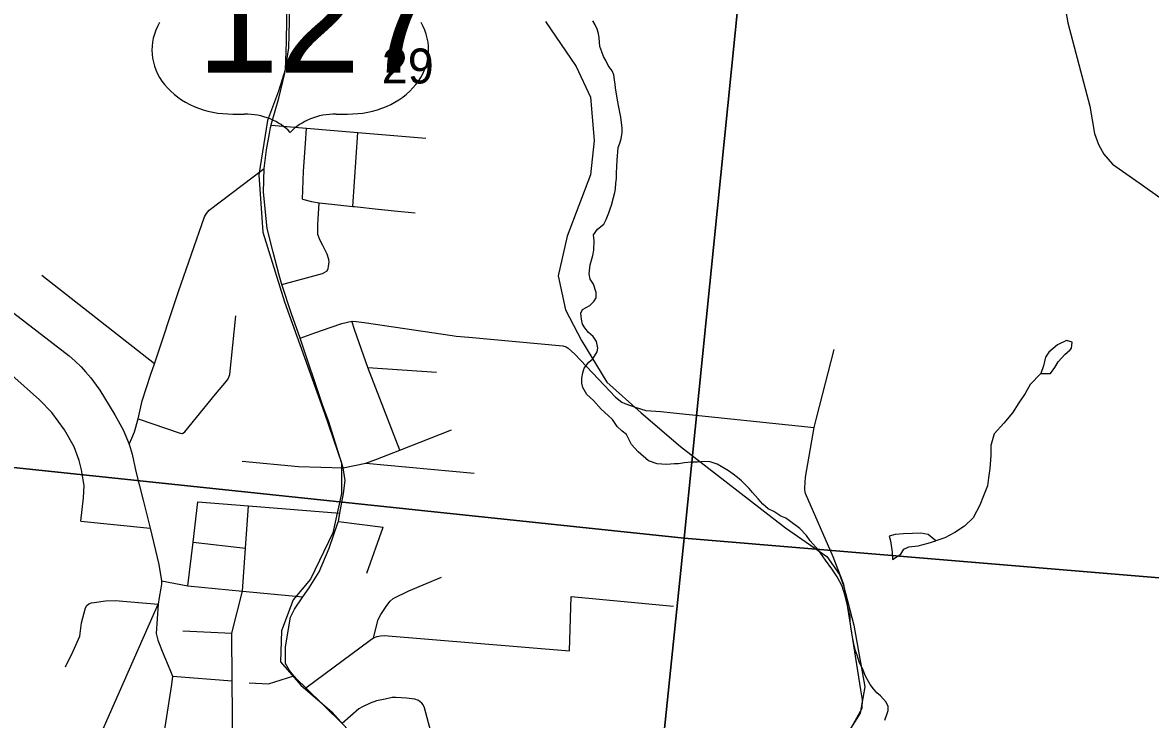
# Model space of a CAD drawing. Extents: x -8.2 to 38.5, y -0.1 to 21.9.
# Drawn here: x 5.146 to 6.498, y 18.858 to 19.692 of the extents above; entities that cross this region are included whole.
import ezdxf

# ---------------------------------------------------------------- set-up
doc = ezdxf.new("R2010")
doc.units = 0
for name, color, linetype in [('GM_X_Adjacent_County_Text', 7, 'Continuous'), ('GM_X_Airport_Location_Class_3', 7, 'Continuous'), ('GM_X_County_Road_Text', 7, 'Continuous'), ('GM_X_Minor_Lake_Text', 7, 'Continuous'), ('GM_X_Minor_River', 7, 'Continuous'), ('GM_X_Township_Road_Text', 7, 'Continuous'), ('GM_X_Township_Subdivision', 7, 'Continuous'), ('GM_X_Township_Subdivision_Text', 7, 'Continuous'), ('GM_X_Township_Text', 7, 'Continuous'), ('GM_X_US_Location', 7, 'Continuous')]:
    doc.layers.add(name, color=color, linetype=linetype)

msp = doc.modelspace()

# ---------------------------------------------------------------- linework, layer by layer
at = {"layer": 'GM_X_Adjacent_County_Text'}
for points in [[(5.0467, 20.1811), (6.0401, 20.072), (5.9396, 19.0747), (4.9457, 19.1792)], [(7.0485, 19.9899), (6.9585, 18.9896), (5.9396, 19.0747), (6.0401, 20.072)], [(5.9396, 19.0747), (5.838, 18.0925), (4.8395, 18.1926), (4.9457, 19.1792)], [(5.9396, 19.0747), (6.9585, 18.9896), (6.8589, 17.9964), (5.838, 18.0925)]]:
    msp.add_lwpolyline(points, close=True, dxfattribs=at)
at = {"layer": 'GM_X_Airport_Location_Class_3'}
for points in [[(5.466, 19.6771), (5.4665, 19.6943), (5.4664, 19.7372), (5.4662, 19.7608), (5.4686, 19.7892), (5.4775, 19.8481), (5.4791, 19.878), (5.4789, 19.9088), (5.4743, 19.9356), (5.47, 19.9472)], [(5.4425, 19.5595), (5.4438, 19.5666), (5.4444, 19.5694), (5.4448, 19.5715), (5.4535, 19.6017), (5.4608, 19.6318), (5.4655, 19.662), (5.466, 19.6771)], [(5.4469, 19.4173), (5.4398, 19.4458), (5.4351, 19.4893), (5.4361, 19.5177), (5.4388, 19.54), (5.4425, 19.5595)], [(5.4572, 19.3784), (5.4539, 19.3898), (5.4469, 19.4173)], [(5.4791, 19.3143), (5.4689, 19.3435), (5.4572, 19.3784)], [(5.5297, 18.8527), (5.4861, 18.8952), (5.4756, 18.9054), (5.4717, 18.9099), (5.4665, 18.9161), (5.4616, 18.9246), (5.4616, 18.9444), (5.4677, 18.9799), (5.4723, 18.9896), (5.4826, 19.0044), (5.49, 19.015), (5.5022, 19.0343), (5.514, 19.0627), (5.5248, 19.0941), (5.525, 19.0948), (5.5268, 19.1045), (5.5312, 19.1281), (5.533, 19.1436), (5.5308, 19.1589), (5.5135, 19.2139), (5.5062, 19.2344), (5.4791, 19.3143)]]:
    msp.add_lwpolyline(points, dxfattribs=at)
at = {"layer": 'GM_X_Minor_Lake_Text'}
for points in [[(6.3671, 19.272), (6.3785, 19.2719), (6.3839, 19.279), (6.3879, 19.2858), (6.3957, 19.2947), (6.4022, 19.3002), (6.4038, 19.3021), (6.4047, 19.3093), (6.3979, 19.3114), (6.3872, 19.3063), (6.3767, 19.2974), (6.3728, 19.2914), (6.3703, 19.2812)], [(6.3703, 19.2812), (6.3671, 19.272)], [(6.2414, 19.0716), (6.2321, 19.0792), (6.2234, 19.0805), (6.2132, 19.0804), (6.2025, 19.0799), (6.1926, 19.0789), (6.1854, 19.0772), (6.1868, 19.0715), (6.1888, 19.0578), (6.1893, 19.049), (6.1993, 19.0556), (6.2029, 19.0616), (6.209, 19.0641), (6.2201, 19.0654), (6.2319, 19.0686)], [(6.2319, 19.0686), (6.2414, 19.0716)]]:
    msp.add_lwpolyline(points, dxfattribs=at)
at = {"layer": 'GM_X_Minor_River'}
for points in [[(5.831, 19.4381), (5.8357, 19.4448), (5.8431, 19.4507), (5.8459, 19.4563), (5.8492, 19.4642), (5.8508, 19.4691), (5.8525, 19.4737), (5.855, 19.4827), (5.8563, 19.4888), (5.8572, 19.4933), (5.8577, 19.4998), (5.8583, 19.5055), (5.8584, 19.512), (5.859, 19.5199), (5.8592, 19.5275), (5.8604, 19.5427), (5.8624, 19.548), (5.8641, 19.5529), (5.8651, 19.5605), (5.8652, 19.5658), (5.8637, 19.5792), (5.861, 19.593), (5.8593, 19.6018), (5.8574, 19.614), (5.8567, 19.6186), (5.8561, 19.6239), (5.8551, 19.6297), (5.8534, 19.6347), (5.8486, 19.6409), (5.8457, 19.6467), (5.8428, 19.6517), (5.8407, 19.6571), (5.8386, 19.6636), (5.8379, 19.669), (5.8377, 19.6739), (5.8367, 19.6793), (5.8353, 19.6843), (5.8328, 19.6897), (5.8302, 19.6943)], [(6.18, 18.8565), (6.1824, 18.8633), (6.1841, 18.8682), (6.1842, 18.8728), (6.1817, 18.8782), (6.175, 18.8856), (6.1706, 18.8895), (6.1665, 18.8942), (6.1625, 18.8992), (6.1567, 18.9093), (6.1531, 18.9185), (6.1499, 18.9255), (6.1471, 18.9343), (6.1449, 18.9397), (6.1429, 18.9482), (6.1412, 18.9562), (6.1399, 18.9658), (6.1387, 18.9745), (6.1385, 18.981), (6.1354, 18.9941), (6.1327, 19.0056), (6.1288, 19.0171), (6.123, 19.0283), (6.1164, 19.038), (6.1091, 19.0481), (6.1007, 19.0601), (6.0907, 19.0715), (6.0863, 19.078), (6.0782, 19.0863), (6.0659, 19.0954), (6.0614, 19.0985), (6.0554, 19.101), (6.0472, 19.1066), (6.0404, 19.1098), (6.0337, 19.1153), (6.0282, 19.1216), (6.0215, 19.1294), (6.0175, 19.134), (6.0127, 19.1391), (6.0082, 19.1434), (6.0034, 19.1474), (5.9982, 19.1513), (5.9926, 19.1553), (5.984, 19.1605), (5.9791, 19.1633), (5.9708, 19.1662), (5.964, 19.1664), (5.9556, 19.1658), (5.9476, 19.1657), (5.94, 19.1651), (5.9327, 19.1638), (5.9281, 19.1636), (5.9182, 19.1631), (5.9072, 19.1638), (5.8967, 19.1671), (5.8844, 19.1781), (5.8763, 19.1867), (5.8705, 19.199), (5.8653, 19.203), (5.8594, 19.2085), (5.8535, 19.217), (5.8483, 19.2217), (5.8402, 19.2292), (5.8309, 19.2394), (5.8228, 19.2468), (5.818, 19.255), (5.8167, 19.2603), (5.8168, 19.2664), (5.8181, 19.2728), (5.8198, 19.2785), (5.8253, 19.2856), (5.83, 19.2896), (5.8352, 19.2979), (5.836, 19.3024), (5.8344, 19.3101), (5.8303, 19.3163), (5.8248, 19.321), (5.8203, 19.3265), (5.8178, 19.3311), (5.8164, 19.3369), (5.8155, 19.3441), (5.8175, 19.3486), (5.8264, 19.3533), (5.8311, 19.3581), (5.8339, 19.3626), (5.834, 19.3691), (5.8309, 19.3791), (5.8269, 19.3849), (5.8255, 19.3914), (5.8269, 19.402), (5.8299, 19.4134), (5.8312, 19.4198), (5.8315, 19.4309), (5.831, 19.4381)], [(6.3671, 19.272), (6.3543, 19.2586), (6.3483, 19.2478), (6.3408, 19.2369), (6.3333, 19.2246), (6.3227, 19.2123), (6.311, 19.1996), (6.3073, 19.1856), (6.307, 19.1735), (6.3059, 19.1583), (6.3044, 19.1469), (6.3031, 19.1374), (6.2982, 19.1254), (6.2938, 19.1141), (6.2858, 19.0991), (6.2757, 19.0891), (6.2641, 19.0814), (6.2518, 19.0752), (6.2414, 19.0716)]]:
    msp.add_lwpolyline(points, dxfattribs=at)
at = {"layer": 'GM_X_Township_Subdivision'}
for p, q in [((5.3987, 19.5827), (5.4124, 19.5827)), ((5.5223, 19.5827), (5.536, 19.5827))]:
    msp.add_line(p, q, dxfattribs=at)
for centre, major_axis, start_param, end_param in [((5.3976, 19.6596), (0.0961, 0), 2.702327, 4.723529), ((5.5371, 19.6596), (-0.0961, 0), 1.559657, 3.580859), ((5.4124, 19.5278), (-0.0687, 0), 3.785094, 4.712389), ((5.5223, 19.5278), (-0.0687, 0), 4.712389, 5.639684)]:
    msp.add_ellipse(centre, major_axis=major_axis, ratio=0.8, start_param=start_param, end_param=end_param, dxfattribs=at)
at = {"layer": 'GM_X_Township_Subdivision_Text'}
for p, q in [((5.5422, 19.4721), (5.5485, 19.5607)), ((5.3045, 19.2836), (5.1694, 19.3892)), ((5.5602, 19.2791), (5.6427, 19.2736)), ((5.5581, 19.1647), (5.688, 19.1527)), ((5.2164, 19.095), (5.2994, 19.0867)), ((5.525, 19.0948), (5.5786, 19.088)), ((5.5593, 19.0327), (5.5786, 19.088)), ((5.3509, 19.0698), (5.4138, 19.0627)), ((5.8021, 18.9395), (5.8039, 19.0048)), ((5.8039, 19.0048), (5.9266, 18.993)), ((5.3387, 18.9635), (5.3972, 18.9608)), ((5.3263, 18.9095), (5.3977, 18.9037))]:
    msp.add_line(p, q, dxfattribs=at)
for points in [[(5.4444, 19.5694), (5.4868, 19.5658), (5.5485, 19.5607), (5.6299, 19.5539)], [(5.4821, 19.4806), (5.4834, 19.5145), (5.4856, 19.5475), (5.4868, 19.5658)], [(5.4821, 19.4806), (5.4927, 19.478), (5.5021, 19.4762), (5.5206, 19.4743), (5.5422, 19.4721), (5.5443, 19.4718), (5.5727, 19.4689), (5.6003, 19.466), (5.6172, 19.4643)], [(5.5116, 19.3951), (5.5126, 19.3976), (5.5132, 19.4002), (5.5139, 19.4055), (5.5134, 19.4083), (5.5117, 19.4148), (5.5064, 19.4251), (5.5031, 19.4312), (5.5004, 19.4384), (5.5005, 19.4503), (5.5021, 19.4762)], [(5.4572, 19.3784), (5.5059, 19.3918), (5.5116, 19.3951)], [(5.2849, 19.2177), (5.3353, 19.2003), (5.338, 19.2002), (5.3411, 19.202), (5.3779, 19.2471), (5.3909, 19.2627), (5.3929, 19.2657), (5.3949, 19.2706), (5.402, 19.3411)], [(5.4791, 19.3143), (5.4968, 19.3207), (5.5164, 19.3275), (5.5293, 19.332), (5.5412, 19.3345), (5.5464, 19.3341), (5.5559, 19.333), (5.6613, 19.3173)], [(5.5986, 19.1802), (5.5602, 19.2791), (5.5446, 19.3233), (5.5412, 19.3345)], [(5.2164, 19.095), (5.2197, 19.1231), (5.2203, 19.1378), (5.2191, 19.1444), (5.2172, 19.1564), (5.2142, 19.1675), (5.2083, 19.1842), (5.1967, 19.2046), (5.1816, 19.2251), (5.1668, 19.2403), (5.1337, 19.27), (5.0743, 19.3158)], [(5.6613, 19.3173), (5.6663, 19.3166), (5.6813, 19.3153), (5.7942, 19.3049), (5.7979, 19.304), (5.8006, 19.3021), (5.8084, 19.2951), (5.8436, 19.2578), (5.8573, 19.2437), (5.865, 19.2376), (5.8685, 19.2359), (5.8806, 19.2314), (5.8934, 19.2276), (5.9116, 19.2264), (5.9265, 19.2249), (6.0953, 19.2071)], [(6.0983, 19.2186), (6.1018, 19.2324), (6.1193, 19.3007)], [(6.1204, 18.8123), (6.1234, 18.8176), (6.1528, 18.8709), (6.1531, 18.8808), (6.1514, 18.893), (6.1347, 18.999), (6.131, 19.0193), (6.1181, 19.0523), (6.0848, 19.1282), (6.084, 19.1323), (6.0842, 19.1348), (6.0848, 19.1477), (6.0953, 19.2071), (6.0983, 19.2186)], [(5.5308, 19.1589), (5.5581, 19.1647), (5.5699, 19.169), (5.5986, 19.1802), (5.6605, 19.2044)], [(5.4097, 19.167), (5.4771, 19.1605), (5.5308, 19.1589)], [(5.3447, 19.0175), (5.3509, 19.0698), (5.3567, 19.1183)], [(5.3567, 19.1183), (5.4174, 19.1134), (5.5268, 19.1045)], [(5.3998, 18.7055), (5.3977, 18.9037), (5.3972, 18.9608), (5.4102, 19.0113), (5.4138, 19.0627), (5.4174, 19.1134)], [(5.3129, 19.0237), (5.3447, 19.0175), (5.4102, 19.0113), (5.4826, 19.0044)], [(5.5673, 18.9551), (5.5726, 18.9771), (5.5758, 18.9832), (5.583, 18.9941), (5.587, 18.9991), (5.5908, 19.0024), (5.6093, 19.0114), (5.6485, 19.0281)], [(5.1978, 18.9207), (5.207, 18.9394), (5.2151, 18.9571), (5.2171, 18.9733), (5.2218, 18.9911), (5.2235, 18.9941), (5.2261, 18.9959), (5.2292, 18.9972), (5.2322, 18.9976)], [(5.2322, 18.9976), (5.246, 18.9995), (5.2573, 18.9999), (5.3089, 18.9955)], [(5.4861, 18.8952), (5.5632, 18.9526), (5.5673, 18.9551), (5.5715, 18.9568), (5.5756, 18.9578), (5.5801, 18.9579), (5.8021, 18.9395)], [(5.4179, 18.9012), (5.4414, 18.9002), (5.4717, 18.9099)], [(5.7034, 18.592), (5.688, 18.649), (5.6774, 18.6885), (5.6642, 18.7376), (5.6623, 18.7446), (5.6282, 18.8714), (5.6268, 18.8749), (5.6251, 18.8771), (5.6212, 18.88), (5.6167, 18.8816), (5.6065, 18.883), (5.594, 18.8838), (5.5896, 18.8837), (5.5811, 18.8818), (5.5709, 18.8796), (5.563, 18.877), (5.554, 18.8727), (5.5495, 18.8702), (5.5297, 18.8527)]]:
    msp.add_lwpolyline(points, dxfattribs=at)
at = {"layer": 'GM_X_Township_Text'}
for points in [[(6.3023, 20.2084), (6.3014, 20.1975), (6.302, 20.1747), (6.3036, 20.1519), (6.305, 20.134), (6.3189, 20.0826), (6.349, 19.9824), (6.3625, 19.9326), (6.376, 19.8759), (6.3826, 19.8222), (6.3906, 19.7489), (6.3945, 19.7196), (6.3995, 19.6922), (6.4258, 19.5921), (6.4312, 19.5594), (6.436, 19.5464), (6.4427, 19.5346), (6.4528, 19.5227), (6.489, 19.4976), (6.7912, 19.2826)], [(5.2742, 19.1872), (5.2776, 19.1943), (5.2806, 19.2022), (5.2849, 19.2177), (5.29, 19.2391), (5.3003, 19.2711), (5.3045, 19.2836), (5.3335, 19.3701), (5.3646, 19.4598), (5.3669, 19.4635), (5.3701, 19.4676), (5.4361, 19.5177)], [(5.1113, 19.3629), (5.2025, 19.2932), (5.2091, 19.2871), (5.2166, 19.2799), (5.2221, 19.274), (5.2282, 19.2668), (5.2348, 19.2578)], [(5.2348, 19.2578), (5.239, 19.2521), (5.2569, 19.2224), (5.267, 19.2043), (5.2742, 19.1872), (5.2778, 19.1752), (5.2824, 19.1544), (5.2911, 19.1202), (5.2994, 19.0867), (5.3099, 19.0433), (5.3129, 19.0237), (5.3129, 19.0196), (5.3124, 19.0149), (5.3104, 19.0034), (5.3089, 18.9955), (5.3066, 18.9603), (5.3086, 18.9526), (5.3147, 18.9374), (5.3232, 18.9174), (5.3263, 18.9095), (5.325, 18.8993), (5.3106, 18.8077)], [(5.1504, 18.6252), (5.1671, 18.6717), (5.1948, 18.7358), (5.2029, 18.7548), (5.3089, 18.9955)]]:
    msp.add_lwpolyline(points, dxfattribs=at)
at = {"layer": 'GM_X_US_Location'}
for points in [[(5.4639, 19.777), (5.4623, 19.6693), (5.4611, 19.6359), (5.4534, 19.61), (5.4402, 19.575), (5.4298, 19.5101), (5.4343, 19.4413), (5.4606, 19.3579), (5.5086, 19.2243), (5.5289, 19.165), (5.5287, 19.1281), (5.5182, 19.0812), (5.4917, 19.0257), (5.471, 19.0006), (5.4569, 18.9636), (5.4557, 18.9267), (5.4802, 18.8984), (5.5176, 18.8663), (5.5638, 18.8147)], [(5.7733, 19.6938), (5.81, 19.6397), (5.8273, 19.603), (5.8316, 19.5511), (5.8273, 19.5101), (5.7992, 19.4366), (5.7884, 19.3891), (5.7971, 19.348), (5.8165, 19.3113), (5.8468, 19.2616), (5.8878, 19.2248), (5.935, 19.1846), (6.0609, 19.0872), (6.1106, 19.0526), (6.1259, 19.0312), (6.1304, 19.0179), (6.143, 18.9705), (6.1559, 18.8964), (6.1506, 18.8652), (6.1185, 18.8143), (6.1151, 18.794), (6.1446, 18.696), (6.2229, 18.4404)]]:
    msp.add_lwpolyline(points, dxfattribs=at)

# ---------------------------------------------------------------- texts
at = {"layer": 'GM_X_County_Road_Text'}
msp.add_text('29', height=0.04186, rotation=0, dxfattribs=at).set_placement((5.5771, 19.6194))
at = {"layer": 'GM_X_Township_Road_Text'}
msp.add_text('127', height=0.000189, rotation=0, dxfattribs=at).set_placement((5.4092, 19.6588))
at = {"layer": 'GM_X_Township_Subdivision'}
msp.add_text('127', height=0.13184, dxfattribs=at).set_placement((5.3555, 19.6322))

doc.saveas('drawing.dxf')
